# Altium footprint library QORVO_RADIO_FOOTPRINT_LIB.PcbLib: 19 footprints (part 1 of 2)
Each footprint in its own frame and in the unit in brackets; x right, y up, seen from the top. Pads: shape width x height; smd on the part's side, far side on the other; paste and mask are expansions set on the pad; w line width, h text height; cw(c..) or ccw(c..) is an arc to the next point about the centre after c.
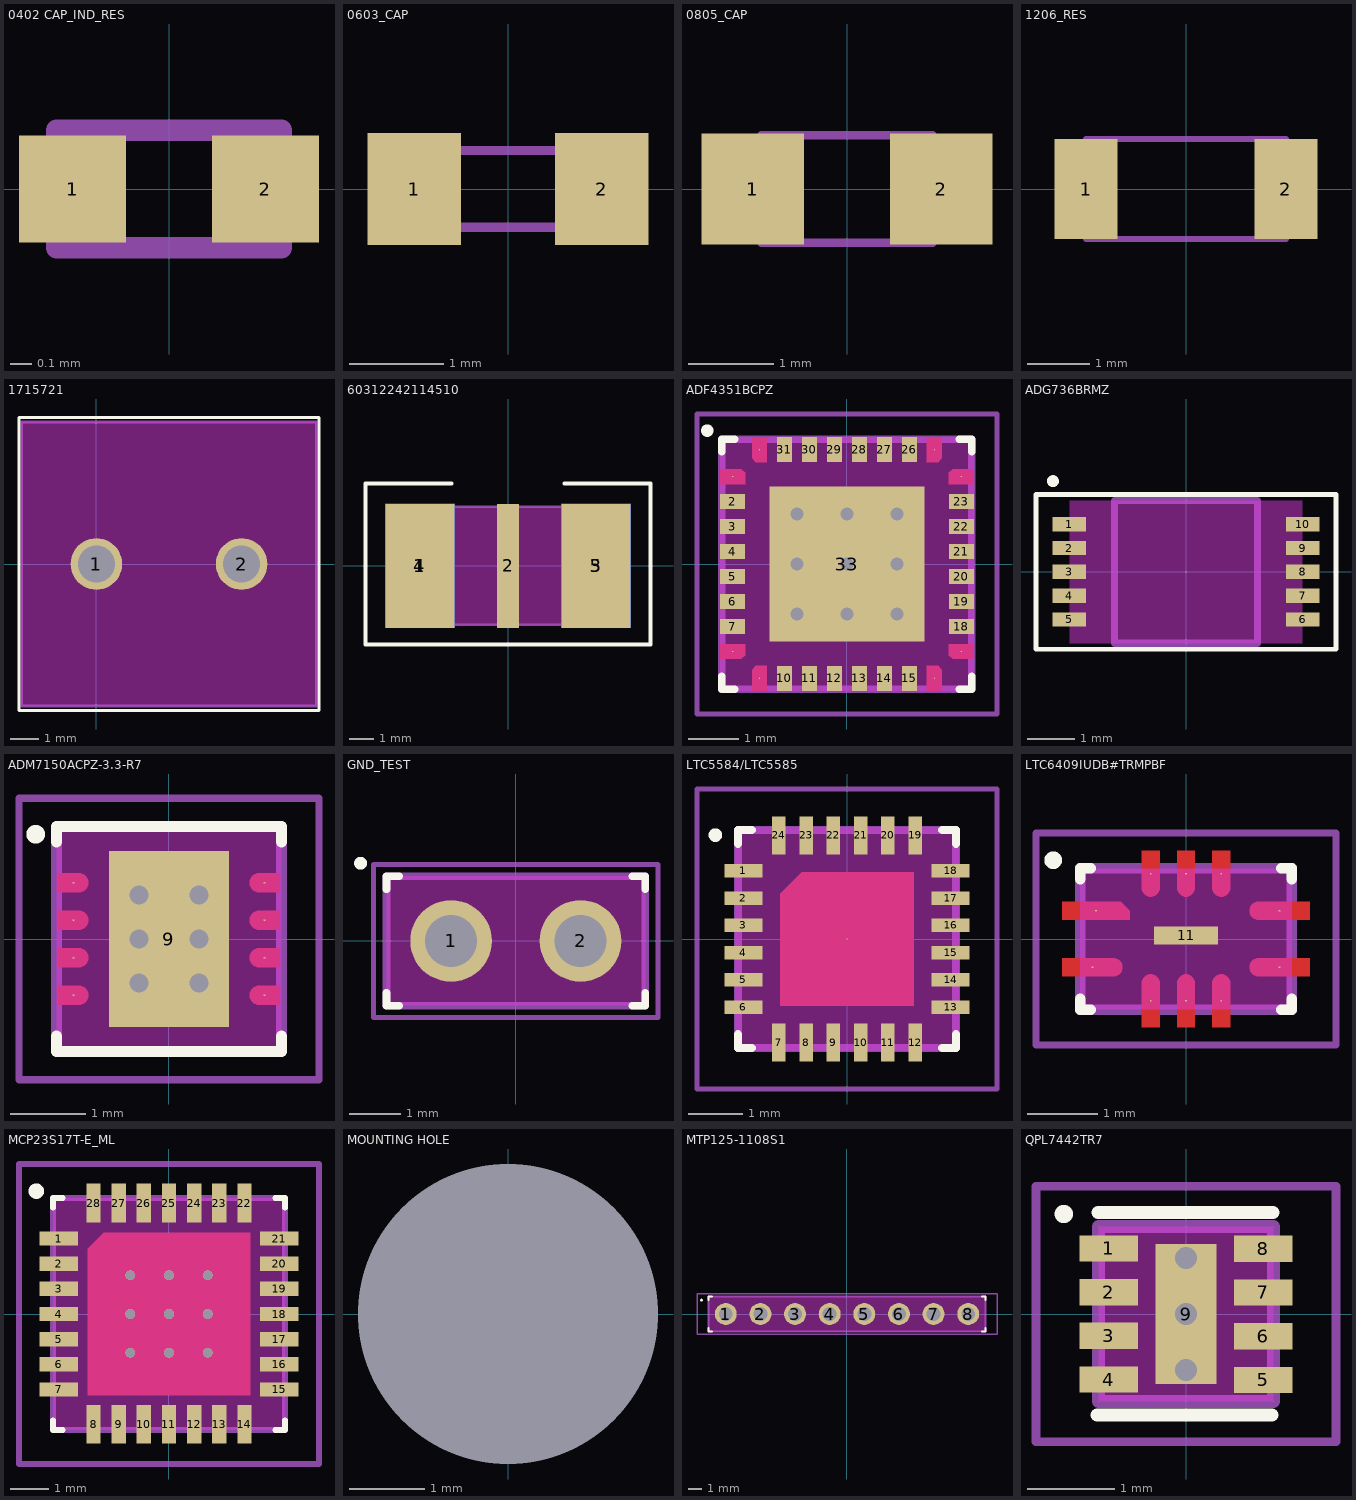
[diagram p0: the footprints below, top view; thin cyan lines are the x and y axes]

## 0402 CAP_IND_RES [mm]
pads (2):
  rect 0.5x0.5 smd mask+0.035: 1(-0.45,0) 2(0.45,0)
Mechanical 1:
  lines w0.1: -0.525,-0.275 0.525,-0.275 0.525,0.275 -0.525,0.275 -0.525,-0.275
3D body "RC0402N_YAG.step": height 0.71, standoff 0, extent -0.527,-0.266 0.539,0.242

## 0603_CAP [mm]
pads (2):
  rect 1x1.2 smd mask+0.035: 1(-1,0) 2(1,0)
Mechanical 1:
  lines w0.1: -0.81,-0.41 0.81,-0.41 0.81,0.41 -0.81,0.41 -0.81,-0.41
3D body "CC0603N_YAG.step": height 0.71, standoff 0, extent -0.8,-0.406 0.8,0.406

## 0805_CAP [mm]
pads (2):
  rect 1.2x1.3 smd mask+0.035: 1(-1.1,0) 2(1.1,0)
Mechanical 1:
  lines w0.1: -1,-0.625 1,-0.625 1,0.625 -1,0.625 -1,-0.625

## 1206_RES [mm]
pads (2):
  rect 1x1.6 smd mask+0.035: 1(-1.6,0) 2(1.6,0)
Mechanical 1:
  lines w0.1: -1.6,-0.8 1.6,-0.8 1.6,0.8 -1.6,0.8 -1.6,-0.8

## 1715721 [mil] "PS CONNECTOR"
pads (2):
  round 71 / inner round 60 / far side round 71 hole 51.18 paste-99999 mask+0: 1(0,0) 2(200,0)
Top Overlay:
  lines w3.94: -106.69,-201.77 306.69,-201.77 306.69,201.77 -106.69,201.77 -106.69,-201.77
Bottom Overlay:
  lines w3.94: -106.69,-201.77 306.69,-201.77 306.69,201.77 -106.69,201.77 -106.69,-201.77
Keep-Out Layer:
  rectangle: -102.95,-195.87 302.95,195.87
Mechanical 15:
  lines w3.94: -102.95,-195.87 302.95,-195.87 302.95,195.87 -102.95,195.87 -102.95,-195.87
3D body "pxc_1715721_05_01_MKDS-1-5-2-5-08_3D.stp": height 559.05, standoff -137.8, extent -121.22,-185 301.22,202.01

## 60312242114510 [mm] "FEMALE SMA - EDGE MOUNT"
pads (5):
  rect 2.8x5 smd mask+0.1: 1(-3.55,0) 3(3.55,0)
  rect 0.9x5 smd mask+0.1: 2(0,0)
  rect 2.8x5 smd far side mask+0.1: 4(-3.55,0) 5(3.55,0)
Top Overlay:
  lines w0.15: -5.75,-3.175 5.75,-3.175 ; -5.75,-3.175 -5.75,3.325 ; -5.75,-3.175 -5.75,3.325 ; -5.75,-3.175 5.75,-3.175 ; -5.75,3.325 -2.269,3.325 -5.75,3.325 ; 5.75,-3.175 5.75,3.325 ; 5.75,-3.175 5.75,3.325 ; 5.75,3.325 2.269,3.325 5.75,3.325
Keep-Out Layer:
  rectangle: -4.76,-2.375 4.76,2.375
Mechanical 15:
  lines w0.1: -4.76,-2.375 4.76,-2.375 4.76,2.375 -4.76,2.375 -4.76,-2.375
3D body "60312242114510_shelding.stp": height 4.36, standoff -3.56, extent -4.76,-15.24 4.76,2.21

## ADF4351BCPZ [mm] "WIDEBAND SYNTHESIZER"
pads (33):
  round 0.025 smd mask+0.05: 1(-2.286,1.75) 8(-2.286,-1.75) 9(-1.75,-2.286) 16(1.75,-2.286) 17(2.286,-1.75) 24(2.286,1.75) 25(1.75,2.286) 32(-1.75,2.286)
  rect 0.5x0.3 smd mask+0.05: 2(-2.286,1.25) 3(-2.286,0.75) 4(-2.286,0.25) 5(-2.286,-0.25) 6(-2.286,-0.75) 7(-2.286,-1.25) 18(2.286,-1.25) 19(2.286,-0.75) 20(2.286,-0.25) 21(2.286,0.25) 22(2.286,0.75) 23(2.286,1.25)
  rect 0.3x0.5 smd mask+0.05: 10(-1.25,-2.286) 11(-0.75,-2.286) 12(-0.25,-2.286) 13(0.25,-2.286) 14(0.75,-2.286) 15(1.25,-2.286) 26(1.25,2.286) 27(0.75,2.286) 28(0.25,2.286) 29(-0.25,2.286) 30(-0.75,2.286) 31(-1.25,2.286)
  rect 3.1x3.1 smd mask+0.05: 33(0,0)
via -1,1 diameter 0.254 hole 0.254
via 0,1 diameter 0.254 hole 0.254
via 1,1 diameter 0.254 hole 0.254
via -1,0 diameter 0.254 hole 0.254
via 0,0 diameter 0.254 hole 0.254
via 1,0 diameter 0.254 hole 0.254
via -1,-1 diameter 0.254 hole 0.254
via 0,-1 diameter 0.254 hole 0.254
via 1,-1 diameter 0.254 hole 0.254
Top Layer:
  region: -1.9,2.111 -1.9,2.536 -1.6,2.536 -1.6,2.036 -1.825,2.036
  region: 1.6,2.036 1.6,2.536 1.9,2.536 1.9,2.111 1.825,2.036
  region: 2.111,1.9 2.536,1.9 2.536,1.6 2.036,1.6 2.036,1.825
  region: 2.036,-1.6 2.536,-1.6 2.536,-1.9 2.111,-1.9 2.036,-1.825
  region: 1.9,-2.111 1.9,-2.536 1.6,-2.536 1.6,-2.036 1.825,-2.036
  region: -1.6,-2.036 -1.6,-2.536 -1.9,-2.536 -1.9,-2.111 -1.825,-2.036
  region: -2.111,-1.9 -2.536,-1.9 -2.536,-1.6 -2.036,-1.6 -2.036,-1.825
  region: -2.036,1.6 -2.536,1.6 -2.536,1.9 -2.111,1.9 -2.036,1.825
Top Overlay:
  circle w0.15: c-2.794,2.667 r0.05
  lines w0.15: -2.5,-2.246 -2.5,-2.5 -2.246,-2.5 ; -2.5,2.246 -2.5,2.5 -2.246,2.5 ; 2.246,-2.5 2.5,-2.5 2.5,-2.246 ; 2.246,2.5 2.5,2.5 2.5,2.246
Bottom Overlay:
  circle w0.15: c-2.794,2.667 r0.05
  lines w0.15: -2.5,-2.246 -2.5,-2.5 -2.246,-2.5 ; -2.5,2.246 -2.5,2.5 -2.246,2.5 ; 2.246,-2.5 2.5,-2.5 2.5,-2.246 ; 2.246,2.5 2.5,2.5 2.5,2.246
Keep-Out Layer:
  rectangle: -2.54,-2.54 2.54,2.54
Mechanical 1:
  lines w0.15: -2.5,-2.5 2.5,-2.5 2.5,2.5 -2.5,2.5 -2.5,-2.5
Mechanical 15:
  lines w0.1: -3,-3 3,-3 3,3 -3,3 -3,-3
3D body "ADF4351BCPZ.stp": height 0.8, standoff 0.05, extent -2.5,-2.5 2.5,2.5

## ADG736BRMZ [mm] "SWITCH - SPDT"
pads (10):
  rect 0.7x0.3 smd mask-2539.97: 1(-2.45,1) 2(-2.45,0.5) 3(-2.45,0) 4(-2.45,-0.5) 5(-2.45,-1) 6(2.45,-1) 7(2.45,-0.5) 8(2.45,0) 9(2.45,0.5) 10(2.45,1)
Top Overlay:
  circle w0.15: c-2.794,1.905 r0.05
  lines w0.1: -3.15,-1.625 -3.15,1.625 3.15,1.625 3.15,-1.625 -3.15,-1.625
Top Solder:
  region: 2.025,-0.7 2.025,-0.3 2.875,-0.3 2.875,-0.7
  region: 2.025,-1.2 2.025,-0.8 2.875,-0.8 2.875,-1.2
  region: 2.025,0.8 2.025,1.2 2.875,1.2 2.875,0.8
  region: 2.025,0.3 2.025,0.7 2.875,0.7 2.875,0.3
  region: 2.025,-0.2 2.025,0.2 2.875,0.2 2.875,-0.2
  region: -2.875,-1.2 -2.875,-0.8 -2.025,-0.8 -2.025,-1.2
  region: -2.875,-0.7 -2.875,-0.3 -2.025,-0.3 -2.025,-0.7
  region: -2.875,0.8 -2.875,1.2 -2.025,1.2 -2.025,0.8
  region: -2.875,0.3 -2.875,0.7 -2.025,0.7 -2.025,0.3
  region: -2.875,-0.2 -2.875,0.2 -2.025,0.2 -2.025,-0.2
Keep-Out Layer:
  rectangle: -2.45,-1.5 2.45,1.5
Mechanical 1:
  lines w0.15: -1.5,-1.5 1.5,-1.5 1.5,1.5 -1.5,1.5 -1.5,-1.5
3D body "ADG736BRMZ.stp": height 1.1, standoff 0, extent -2.45,-1.5 2.45,1.5

## ADM7150ACPZ-3.3-R7 [mm] "3.3V REG"
pads (9):
  round 0.025 smd mask+0.05: 1(-1.275,0.75) 2(-1.275,0.25) 3(-1.275,-0.25) 4(-1.275,-0.75) 5(1.275,-0.75) 6(1.275,-0.25) 7(1.275,0.25) 8(1.275,0.75)
  rect 1.6x2.34 smd mask+0.1: 9(0,0)
via 0.4,-0.585 diameter 0.254 hole 0.254
via -0.4,-0.585 diameter 0.254 hole 0.254
via 0.4,0.585 diameter 0.254 hole 0.254
via -0.4,0.585 diameter 0.254 hole 0.254
via 0.4,0 diameter 0.254 hole 0.254
via -0.4,0 diameter 0.254 hole 0.254
Top Layer:
  region: -1.2,0.625 -1.475,0.625 -1.475,0.875 -1.2,0.875 -1.175,0.875 -1.129,0.856 -1.094,0.821 -1.075,0.775 -1.075,0.75 -1.075,0.725 -1.094,0.679 -1.129,0.644 -1.175,0.625
  region: -1.2,0.125 -1.475,0.125 -1.475,0.375 -1.2,0.375 -1.175,0.375 -1.129,0.356 -1.094,0.321 -1.075,0.275 -1.075,0.25 -1.075,0.225 -1.094,0.179 -1.129,0.144 -1.175,0.125
  region: -1.2,-0.375 -1.475,-0.375 -1.475,-0.125 -1.2,-0.125 -1.175,-0.125 -1.129,-0.144 -1.094,-0.179 -1.075,-0.225 -1.075,-0.25 -1.075,-0.275 -1.094,-0.321 -1.129,-0.356 -1.175,-0.375
  region: -1.2,-0.875 -1.475,-0.875 -1.475,-0.625 -1.2,-0.625 -1.175,-0.625 -1.129,-0.644 -1.094,-0.679 -1.075,-0.725 -1.075,-0.75 -1.075,-0.775 -1.094,-0.821 -1.129,-0.856 -1.175,-0.875
  region: 1.2,-0.625 1.475,-0.625 1.475,-0.875 1.2,-0.875 1.175,-0.875 1.129,-0.856 1.094,-0.821 1.075,-0.775 1.075,-0.75 1.075,-0.725 1.094,-0.679 1.129,-0.644 1.175,-0.625
  region: 1.2,-0.125 1.475,-0.125 1.475,-0.375 1.2,-0.375 1.175,-0.375 1.129,-0.356 1.094,-0.321 1.075,-0.275 1.075,-0.25 1.075,-0.225 1.094,-0.179 1.129,-0.144 1.175,-0.125
  region: 1.2,0.375 1.475,0.375 1.475,0.125 1.2,0.125 1.175,0.125 1.129,0.144 1.094,0.179 1.075,0.225 1.075,0.25 1.075,0.275 1.094,0.321 1.129,0.356 1.175,0.375
  region: 1.2,0.875 1.475,0.875 1.475,0.625 1.2,0.625 1.175,0.625 1.129,0.644 1.094,0.679 1.075,0.725 1.075,0.75 1.075,0.775 1.094,0.821 1.129,0.856 1.175,0.875
Top Overlay:
  circle w0.15: c-1.778,1.397 r0.05
  lines w0.15: -1.5,-1.294 -1.5,-1.5 1.5,-1.5 1.5,-1.294 ; -1.5,1.294 -1.5,1.5 1.5,1.5 1.5,1.294
Bottom Overlay:
  circle w0.15: c-1.778,1.397 r0.05
  lines w0.15: -1.5,-1.294 -1.5,-1.5 1.5,-1.5 1.5,-1.294 ; -1.5,1.294 -1.5,1.5 1.5,1.5 1.5,1.294
Keep-Out Layer:
  rectangle: -1.5,-1.5 1.5,1.5
Mechanical 1:
  lines w0.15: -1.5,-1.5 -1.5,1.5 1.5,1.5 1.5,-1.5 -1.5,-1.5
Mechanical 15:
  lines w0.1: -2,-1.875 2,-1.875 2,1.875 -2,1.875 -2,-1.875
3D body "ADM7150ACPZ-3.3-R7.stp": height 0.85, standoff 0, extent -1.55,-1.5 1.55,1.5

## GND_TEST [mm] "TEST POINT FOR GND HEADER"
pads (2):
  round 1.605 hole 1.02: 1(-1.27,0) 2(1.27,0)
Top Overlay:
  circle w0.15: c-3.048,1.524 r0.05
  lines w0.15: -2.54,-1.016 -2.54,-1.27 -2.286,-1.27 ; -2.54,1.016 -2.54,1.27 -2.286,1.27 ; 2.286,-1.27 2.54,-1.27 2.54,-1.016 ; 2.286,1.27 2.54,1.27 2.54,1.016
Bottom Overlay:
  lines w0.15: -2.54,-1.016 -2.54,-1.27 -2.286,-1.27 ; -2.54,1.016 -2.54,1.27 -2.286,1.27 ; 2.286,-1.27 2.54,-1.27 2.54,-1.016 ; 2.286,1.27 2.54,1.27 2.54,1.016
Keep-Out Layer:
  rectangle: -2.54,-1.27 2.54,1.27
Mechanical 1:
  lines w0.15: -2.54,-1.27 -2.54,1.27 2.54,1.27 2.54,-1.27 -2.54,-1.27
Mechanical 15:
  lines w0.1: -2.79,-1.5 2.79,-1.5 2.79,1.5 -2.79,1.5 -2.79,-1.5
3D body "M20-9990245.step": height 8.65, standoff -3.03, extent -2.573,-1.263 2.507,1.277

## LTC5584/LTC5585 [mm] "MIXERS /  / LTC5585IUF#PBF / LTC5584IUF#PBF"
pads (25):
  rect 0.7x0.25 smd mask+0.05: 1(-1.9,1.25) 2(-1.9,0.75) 3(-1.9,0.25) 4(-1.9,-0.25) 5(-1.9,-0.75) 6(-1.9,-1.25) 13(1.9,-1.25) 14(1.9,-0.75) 15(1.9,-0.25) 16(1.9,0.25) 17(1.9,0.75) 18(1.9,1.25)
  rect 0.25x0.7 smd mask+0.05: 7(-1.25,-1.9) 8(-0.75,-1.9) 9(-0.25,-1.9) 10(0.25,-1.9) 11(0.75,-1.9) 12(1.25,-1.9) 19(1.25,1.9) 20(0.75,1.9) 21(0.25,1.9) 22(-0.25,1.9) 23(-0.75,1.9) 24(-1.25,1.9)
  round 0.025 smd mask-2539.97: 25(0,0)
Top Layer:
  region: 1.225,1.225 1.225,-1.225 -1.225,-1.225 -1.225,0.825 -0.825,1.225
Top Overlay:
  circle w0.15: c-2.413,1.905 r0.05
  lines w0.15: -2,-1.746 -2,-2 -1.746,-2 ; -2,1.746 -2,2 -1.746,2 ; 1.746,-2 2,-2 2,-1.746 ; 1.746,2 2,2 2,1.746
Top Solder:
  region: -1.25,-1.25 -1.25,1.25 1.25,1.25 1.25,-1.25
Keep-Out Layer:
  rectangle: -2.05,-2.05 2.05,2.05
Mechanical 1:
  lines w0.15: -2,-2 2,-2 2,2 -2,2 -2,-2
Mechanical 15:
  lines w0.1: -2.75,-2.75 2.75,-2.75 2.75,2.75 -2.75,2.75 -2.75,-2.75
3D body "LTC5585IUF#PBF.step": height 0.8, standoff 0, extent -2.05,-2.05 2.05,2.05

## LTC6409IUDB#TRMPBF [mm] "DIFFERENTAL OP-AMP"
height 0.8
pads (11):
  round 0.025 smd mask-2539.97: 1(-1.275,0.4) 2(-1.325,-0.4) 3(-0.5,-0.875) 4(0,-0.875) 5(0.5,-0.875) 6(1.325,-0.4) 7(1.325,0.4) 8(0.5,0.925) 9(0,0.925) 10(-0.5,0.925)
  rect 0.9x0.25 smd mask-2539.97: 11(0,0.05)
Top Layer:
  region: 1.025,0.525 1.75,0.525 1.75,0.275 1.025,0.275 1,0.275 0.954,0.294 0.919,0.329 0.9,0.375 0.9,0.4 0.9,0.425 0.919,0.471 0.954,0.506 1,0.525
  region: 1.025,-0.275 1.75,-0.275 1.75,-0.525 1.025,-0.525 1,-0.525 0.954,-0.506 0.919,-0.471 0.9,-0.425 0.9,-0.4 0.9,-0.375 0.919,-0.329 0.954,-0.294 1,-0.275
  region: 0.625,-0.625 0.625,-1.25 0.375,-1.25 0.375,-0.625 0.375,-0.6 0.394,-0.554 0.429,-0.519 0.475,-0.5 0.5,-0.5 0.525,-0.5 0.571,-0.519 0.606,-0.554 0.625,-0.6
  region: 0.125,-0.625 0.125,-1.25 -0.125,-1.25 -0.125,-0.625 -0.125,-0.6 -0.106,-0.554 -0.071,-0.519 -0.025,-0.5 0,-0.5 0.025,-0.5 0.071,-0.519 0.106,-0.554 0.125,-0.6
  region: -0.375,-0.625 -0.375,-1.25 -0.625,-1.25 -0.625,-0.625 -0.625,-0.6 -0.606,-0.554 -0.571,-0.519 -0.525,-0.5 -0.5,-0.5 -0.475,-0.5 -0.429,-0.519 -0.394,-0.554 -0.375,-0.6
  region: -1.025,-0.525 -1.75,-0.525 -1.75,-0.275 -1.025,-0.275 -1,-0.275 -0.954,-0.294 -0.919,-0.329 -0.9,-0.375 -0.9,-0.4 -0.9,-0.425 -0.919,-0.471 -0.954,-0.506 -1,-0.525
  region: -0.8,0.275 -1.75,0.275 -1.75,0.525 -0.925,0.525 -0.8,0.4
  region: 0.375,0.725 0.375,1.25 0.625,1.25 0.625,0.725 0.625,0.7 0.606,0.654 0.571,0.619 0.525,0.6 0.5,0.6 0.475,0.6 0.429,0.619 0.394,0.654 0.375,0.7
  region: -0.125,0.725 -0.125,1.25 0.125,1.25 0.125,0.725 0.125,0.7 0.106,0.654 0.071,0.619 0.025,0.6 0,0.6 -0.025,0.6 -0.071,0.619 -0.106,0.654 -0.125,0.7
  region: -0.625,0.725 -0.625,1.25 -0.375,1.25 -0.375,0.725 -0.375,0.7 -0.394,0.654 -0.429,0.619 -0.475,0.6 -0.5,0.6 -0.525,0.6 -0.571,0.619 -0.606,0.654 -0.625,0.7
Top Overlay:
  circle w0.15: c-1.882,1.116 r0.05
  lines w0.15: -1.5,-0.85 -1.5,-1 -1.35,-1 ; -1.5,0.85 -1.5,1 -1.35,1 ; 1.35,-1 1.5,-1 1.5,-0.85 ; 1.35,1 1.5,1 1.5,0.85
Top Solder:
  drawing of 11 lines, arcs and shapes, not listed
Keep-Out Layer:
  rectangle: -1.5,-1 1.5,1
Mechanical 1:
  lines w0.15: -1.5,-1 1.5,-1 1.5,1 -1.5,1 -1.5,-1
Mechanical 15:
  lines w0.1: -2.125,-1.5 2.125,-1.5 2.125,1.5 -2.125,1.5 -2.125,-1.5
3D body: height 0.8, standoff 0.05, extent -1.524,-1.016 1.524,1.016
3D body: height 0.8, standoff 0.05, extent -1.524,-1.016 1.524,1.016

## MCP23S17T-E_ML [mm] "I/O EXPANDER"
pads (29):
  rect 1x0.37 smd mask+0.04: 1(-2.85,1.95) 2(-2.85,1.3) 3(-2.85,0.65) 4(-2.85,0) 5(-2.85,-0.65) 6(-2.85,-1.3) 7(-2.85,-1.95) 15(2.85,-1.95) 16(2.85,-1.3) 17(2.85,-0.65) 18(2.85,0) 19(2.85,0.65) 20(2.85,1.3) 21(2.85,1.95)
  rect 0.37x1 smd mask+0.04: 8(-1.95,-2.85) 9(-1.3,-2.85) 10(-0.65,-2.85) 11(0,-2.85) 12(0.65,-2.85) 13(1.3,-2.85) 14(1.95,-2.85) 22(1.95,2.865) 23(1.3,2.865) 24(0.65,2.865) 25(0,2.865) 26(-0.65,2.865) 27(-1.3,2.865) 28(-1.95,2.865)
  round 0.025 smd mask-2539.97: 29(0,0)
via 1,0 diameter 0.254 hole 0.254
via 1,-1 diameter 0.254 hole 0.254
via 0,-1 diameter 0.254 hole 0.254
via -1,-1 diameter 0.254 hole 0.254
via 1,1 diameter 0.254 hole 0.254
via 0,0 diameter 0.254 hole 0.254
via -1,0 diameter 0.254 hole 0.254
via 0,1 diameter 0.254 hole 0.254
via -1,1 diameter 0.254 hole 0.254
Top Layer:
  region: 2.1,2.1 2.1,-2.1 -2.1,-2.1 -2.1,1.68 -1.68,2.1
Top Overlay:
  circle w0.2: c-3.429,3.175 r0.1
  lines w0.15: -3,-2.746 -3,-3 -2.746,-3 ; -3,2.746 -3,3 -2.746,3 ; 2.746,-3 3,-3 3,-2.746 ; 2.746,3 3,3 3,2.746
Top Solder:
  region: -2.125,-2.125 -2.125,2.125 2.125,2.125 2.125,-2.125
Keep-Out Layer:
  rectangle: -3,-3 3,3
Mechanical 1:
  lines w0.15: -3,-3 3,-3 3,3 -3,3 -3,-3
Mechanical 15:
  lines w0.15: -3.875,-3.875 3.875,-3.875 3.875,3.875 -3.875,3.875 -3.875,-3.875
3D body "MCP23S17T-E_ML.stp": height 1, standoff 0, extent -3.056,-3.056 3.044,3.044

## MOUNTING HOLE [mm] "NOT CONNECTED TP GROUND"
pads (1):
  round 0 hole 4 unplated paste-2539.97: MH(0,0)

## MTP125-1108S1 [mm] "Direct Insert Policy 2.5mm 8P 6mm -40℃~+105℃ 3mm 2.54mm Single Row Black Brass 1x8P Plugin,P=2.54mm Pin Headers ROHS"
pads (8):
  round 1.605 hole 1.02: 1(-8.89,0) 2(-6.35,0) 3(-3.81,0) 4(-1.27,0) 5(1.27,0) 6(3.81,0) 7(6.35,0) 8(8.89,0)
Top Overlay:
  circle w0.15: c-10.668,1.016 r0.03
  lines w0.15: -10.16,-1.016 -10.16,-1.27 -9.906,-1.27 ; -10.16,1.016 -10.16,1.27 -9.906,1.27 ; 9.906,-1.27 10.16,-1.27 10.16,-1.016 ; 9.906,1.27 10.16,1.27 10.16,1.016
Bottom Overlay:
  lines w0.15: -10.16,-1.016 -10.16,-1.27 -9.906,-1.27 ; -10.16,1.016 -10.16,1.27 -9.906,1.27 ; 9.906,-1.27 10.16,-1.27 10.16,-1.016 ; 9.906,1.27 10.16,1.27 10.16,1.016
Keep-Out Layer:
  rectangle: -10.16,-1.27 10.16,1.27
Mechanical 1:
  lines w0.15: -10.16,-1.27 10.16,-1.27 10.16,1.27 -10.16,1.27 -10.16,-1.27
Mechanical 15:
  lines w0.1: -11,-1.5 11,-1.5 11,1.5 -11,1.5 -11,-1.5
3D body "m20-9990845.stp": height 8.64, standoff -3.04, extent -10.185,-1.313 10.135,1.227

## QPL7442TR7 [mm] "LNA"
pads (9):
  rect 0.67x0.3 smd mask+0.05: 1(-0.885,0.75) 2(-0.885,0.25) 3(-0.885,-0.25) 4(-0.885,-0.75) 5(0.885,-0.754) 6(0.885,-0.254) 7(0.885,0.246) 8(0.885,0.746)
  rect 0.7x1.6 smd mask+0.05: 9(0,0)
via 0,-0.64 diameter 0.254 hole 0.254
via 0,0.64 diameter 0.254 hole 0.254
via 0,0 diameter 0.254 hole 0.254
Top Overlay:
  circle w0.15: c-1.397,1.143 r0.03
  lines w0.15: -1.017,-1.156 0.983,-1.156 ; -1.004,1.162 0.996,1.162
Keep-Out Layer:
  rectangle: -1,-1 1,1
Mechanical 1:
  lines w0.15: -1,-1 1,-1 1,1 -1,1 -1,-1
Mechanical 15:
  lines w0.1: -1.714,-1.46 1.714,-1.46 1.714,1.46 -1.714,1.46 -1.714,-1.46
3D body "QPL7442TR7.stp": height 0.95, standoff 0, extent -1.05,-1 1.05,1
